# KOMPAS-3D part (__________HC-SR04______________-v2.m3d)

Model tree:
1. Держатель-боковая грань
2. Операция выдавливания:держатель
     Расстояние 1 = 50
3. Панель крепления датчика-боковая грань
4. Операция выдавливания:боковая грань
     Расстояние 1 = 50
5. Отверстия для сенсоров
6. Вырезать элемент выдавливания:отверстия сенсоров
     Расстояние 1 = 3
7. Скругление:1
     Радиус = 2
